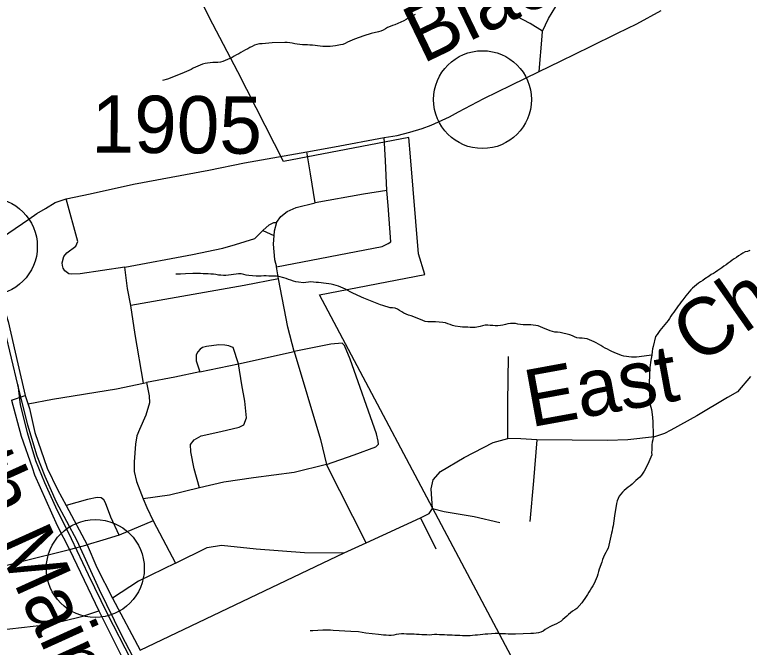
# Model space of a CAD drawing. Extents: x 1379453 to 1387082, y 594364 to 596664.
# Drawn here: x 1380115.2 to 1380304.5, y 596180.5 to 596343.6 of the extents above; entities that cross this region are included whole.
import ezdxf

# ---------------------------------------------------------------- set-up
doc = ezdxf.new("R2010")
doc.units = 0
for name, color, linetype in [('Old_Level_11', 7, 'Continuous'), ('Old_Level_29', 7, 'Continuous'), ('Old_Level_32', 7, 'Continuous'), ('Old_Level_35', 7, 'Continuous'), ('Old_Level_44', 7, 'Continuous'), ('Old_Level_48', 7, 'Continuous'), ('Old_Level_49', 7, 'Continuous'), ('Old_Level_62', 7, 'Continuous'), ('Old_Level_8', 7, 'Continuous')]:
    doc.layers.add(name, color=color, linetype=linetype)

msp = doc.modelspace()

# ---------------------------------------------------------------- linework, layer by layer
at = {"layer": 'Old_Level_29'}
for points in [[(1380108.46, 596283.82), (1380111.76, 596270.24), (1380113.55, 596264.52), (1380116.02, 596253.56), (1380117.97, 596245.42)], [(1380117.97, 596245.42), (1380119.03, 596242.08), (1380120.4, 596235.9), (1380123.6, 596226.7), (1380126.24, 596221.18), (1380128.47, 596217.04), (1380133.91, 596206.95)], [(1380133.91, 596206.95), (1380136.38, 596201.11), (1380140.4, 596193.23), (1380147.53, 596179.82)]]:
    msp.add_lwpolyline(points, dxfattribs=at)
at = {"layer": 'Old_Level_32'}
for p, q in [((1380114.41, 596244.19), (1380117.97, 596245.42)), ((1380129.39, 596205.72), (1380133.91, 596206.95))]:
    msp.add_line(p, q, dxfattribs=at)
for points in [[(1380108.46, 596283.82), (1380118.87, 596290.87), (1380120.9, 596292.35), (1380123.15, 596293.62), (1380125.67, 596295.15), (1380128.47, 596296.14), (1380134.69, 596297.38), (1380145.88, 596299.86), (1380165.23, 596303.54), (1380174.41, 596305.44), (1380190.5, 596308.25), (1380197.64, 596309.56), (1380210.38, 596311.91), (1380213.74, 596312.43), (1380217.05, 596313.31), (1380220.2, 596314.25), (1380222.51, 596315.09), (1380227.24, 596317.29), (1380229.53, 596318.56), (1380236.12, 596321.94), (1380243.15, 596325.43), (1380250.35, 596328.92), (1380255.87, 596331.62), (1380263.54, 596335.36), (1380270.53, 596338.81), (1380275.52, 596341.25), (1380281.78, 596344.7)], [(1380242.31, 596234.37), (1380242.26, 596243.65), (1380242.48, 596255.48)], [(1380304.79, 596250.29), (1380301.41, 596246.4), (1380298.84, 596244.9), (1380291, 596240.23), (1380284.25, 596236.51), (1380282.6, 596235.67), (1380280.03, 596234.79), (1380273.2, 596234.03), (1380267.91, 596233.86), (1380249.74, 596234)], [(1380114.41, 596244.19), (1380116.9, 596234.95), (1380119.71, 596226.84), (1380120.31, 596224.99), (1380126.21, 596211.97), (1380129.39, 596205.72)], [(1380249.74, 596234), (1380245.59, 596234.27), (1380242.31, 596234.37)], [(1380249.74, 596234), (1380248.85, 596223.47), (1380247.95, 596212.95)], [(1380026.39, 596181.13), (1380049.77, 596192.89), (1380056.42, 596196.44), (1380059.77, 596198.34), (1380063.44, 596200.24), (1380066.91, 596200.02), (1380069.73, 596199.5), (1380071.26, 596198.68), (1380073.42, 596196.48), (1380075.56, 596193.36), (1380079.48, 596193.92), (1380087.21, 596195.33), (1380090.9, 596196.15), (1380093.23, 596196.62), (1380116.89, 596202.64), (1380129.39, 596205.72)], [(1380129.39, 596205.72), (1380136.89, 596189.9), (1380142.92, 596177.94)]]:
    msp.add_lwpolyline(points, dxfattribs=at)
for centre in [(1380235.75, 596321.69), (1380108.46, 596283.82), (1380136.01, 596200.86)]:
    msp.add_circle(centre, 12.61, dxfattribs=at)
at = {"layer": 'Old_Level_35'}
for p, q in [((1380179.2, 596287.95), (1380181.99, 596286.69)), ((1380183.22, 596275.48), (1380182.66, 596278.59)), ((1380172.93, 596253.58), (1380187.24, 596256.79)), ((1380162.91, 596251.56), (1380172.93, 596253.58)), ((1380148.43, 596248.59), (1380149.2, 596248.75)), ((1380205.74, 596207.5), (1380195.52, 596227.64)), ((1380150.9, 596213.17), (1380142.16, 596209.41)), ((1380150.9, 596213.17), (1380156.64, 596202.2)), ((1380205.74, 596207.5), (1380219.74, 596213.92)), ((1380219.74, 596213.92), (1380223.74, 596205.9)), ((1380200.14, 596204.85), (1380205.74, 596207.5))]:
    msp.add_line(p, q, dxfattribs=at)
for points in [[(1380251.23, 596339.32), (1380252.72, 596342.56), (1380254.63, 596345.69), (1380255.48, 596347.21)], [(1380251.23, 596339.32), (1380248, 596341.28), (1380244.56, 596343.14)], [(1380250.35, 596328.92), (1380251.11, 596338.01), (1380251.23, 596339.32)], [(1380211.09, 596298.26), (1380210.78, 596305.98), (1380210.38, 596311.91)], [(1380192.62, 596295.07), (1380191.46, 596302.53), (1380190.5, 596308.25)], [(1380182.66, 596278.59), (1380209.89, 596283.86), (1380211.48, 596284.58), (1380212.15, 596285.06), (1380211.48, 596294.43), (1380211.09, 596298.26)], [(1380211.09, 596298.26), (1380205.05, 596297.33), (1380192.62, 596295.07)], [(1380143.61, 596278.55), (1380132.1, 596276.81), (1380129.78, 596276.71), (1380129.22, 596276.81), (1380128.12, 596277.56), (1380127.74, 596278.21), (1380127.53, 596278.94), (1380127.47, 596279.66), (1380127.92, 596281.25), (1380128.66, 596282.19), (1380131.03, 596283.96), (1380131.47, 596285.15), (1380128.47, 596296.14)], [(1380182.69, 596290.05), (1380183.8, 596291.59), (1380185.41, 596292.82), (1380187.73, 596293.92), (1380192.62, 596295.07)], [(1380179.2, 596287.95), (1380180.76, 596289.44), (1380181.99, 596290.05), (1380182.69, 596290.05)], [(1380182.69, 596290.05), (1380182.06, 596287.81), (1380181.99, 596286.69)], [(1380143.61, 596278.55), (1380161, 596281.81), (1380168.89, 596283.42), (1380172.11, 596284.37), (1380177.08, 596285.92), (1380179.2, 596287.95)], [(1380181.99, 596286.69), (1380181.84, 596284.45), (1380182.2, 596280.47), (1380182.66, 596278.59)], [(1380145.16, 596268.66), (1380144.32, 596273.01), (1380143.61, 596278.55)], [(1380183.22, 596275.48), (1380174.37, 596273.82), (1380145.16, 596268.66)], [(1380187.24, 596256.79), (1380185.58, 596263.08), (1380183.22, 596275.48)], [(1380148.43, 596248.59), (1380146.3, 596261.19), (1380145.16, 596268.66)], [(1380172.93, 596253.58), (1380171.55, 596257.8), (1380171.03, 596257.98), (1380170.39, 596258.24), (1380169.36, 596258.43), (1380167.84, 596258.47), (1380164.62, 596258.08), (1380163.66, 596257.79), (1380163, 596257.34), (1380162.43, 596256.72), (1380162, 596255.93), (1380161.96, 596254.41), (1380162.91, 596251.56)], [(1380195.52, 596227.64), (1380202.69, 596230.13), (1380208.23, 596232.2), (1380208.94, 596232.88), (1380208.9, 596233.66), (1380208.4, 596235.52), (1380201.68, 596254.84), (1380200.18, 596258.34), (1380199.63, 596258.91), (1380196.66, 596258.68), (1380187.24, 596256.79)], [(1380187.24, 596256.79), (1380194.03, 596234.12), (1380195.52, 596227.64)], [(1380162.87, 596221.63), (1380161.47, 596226.56), (1380160.63, 596230.91), (1380160.53, 596232.83), (1380161.44, 596234.01), (1380163.31, 596235.07), (1380168.38, 596236.12), (1380173.06, 596237.27), (1380174.28, 596237.88), (1380174.98, 596239.7), (1380174.54, 596243.95), (1380173.78, 596248.14), (1380172.93, 596253.58)], [(1380162.91, 596251.56), (1380156.53, 596250.12), (1380149.2, 596248.75)], [(1380149.2, 596248.75), (1380149.88, 596245.32), (1380149.99, 596243.52), (1380149, 596240.35), (1380147.43, 596236.69), (1380146.74, 596235.02), (1380146.37, 596232.9), (1380145.99, 596228.37), (1380146, 596225.81), (1380146.64, 596223.23), (1380148.37, 596218.82)], [(1380118.71, 596243.28), (1380125.01, 596244.47), (1380141.43, 596247.14), (1380148.43, 596248.59)], [(1380222.89, 596216.29), (1380222.56, 596221.39), (1380223.02, 596223.72), (1380224.93, 596225.83), (1380231.04, 596229.49), (1380238.51, 596233.35), (1380242.31, 596234.37)], [(1380195.52, 596227.64), (1380187.19, 596225.59), (1380176.78, 596224.18), (1380169.1, 596223.07), (1380162.87, 596221.63)], [(1380162.87, 596221.63), (1380155.12, 596219.76), (1380148.37, 596218.82)], [(1380142.16, 596209.41), (1380139.99, 596214.1), (1380138.61, 596217.78), (1380138.17, 596218.53), (1380137.53, 596219.04), (1380136.51, 596219.11), (1380134.02, 596218.63), (1380128.47, 596217.04)], [(1380148.37, 596218.82), (1380149.24, 596216.58), (1380150.9, 596213.17)], [(1380219.74, 596213.92), (1380220.99, 596214.5), (1380221.97, 596215.03), (1380222.89, 596216.29)], [(1380222.89, 596216.29), (1380225.91, 596215.55), (1380233.64, 596214.29), (1380240.24, 596212.73)], [(1380142.16, 596209.41), (1380137.92, 596208.14), (1380133.91, 596206.95)], [(1380156.64, 596202.2), (1380164.79, 596206.28), (1380168.49, 596206.82), (1380177.44, 596205.92), (1380189.9, 596204.99), (1380200.14, 596204.85)], [(1380147.53, 596179.82), (1380192.75, 596201.39), (1380200.14, 596204.85)], [(1380156.64, 596202.2), (1380147.09, 596197.6), (1380140.4, 596193.23)], [(1380081.13, 596177.69), (1380088.66, 596180.11), (1380095.22, 596182.48), (1380100.19, 596184.55), (1380113.97, 596185.32), (1380122.99, 596186.36), (1380127.57, 596187.25), (1380132.78, 596188.54), (1380136.89, 596189.9)]]:
    msp.add_lwpolyline(points, dxfattribs=at)
at = {"layer": 'Old_Level_44'}
for points in [[(1380116.06, 596248.21), (1380112.78, 596261.93), (1380109.32, 596275.15), (1380106.26, 596288.21), (1380103.83, 596298.21), (1380102.17, 596307.22), (1380102.03, 596316.04), (1380101.94, 596323.8), (1380102.14, 596330.6), (1380103.22, 596337.78), (1380105.24, 596346.36), (1380107.03, 596355.59), (1380107.3, 596362.39), (1380107.51, 596369.43), (1380106.53, 596377.3), (1380104.36, 596387.78), (1380101.51, 596396.99), (1380098.46, 596405.32), (1380096.21, 596409.95), (1380082.73, 596438.92), (1380082.12, 596440.37)], [(1380198.66, 596068.96), (1380192.47, 596082.12), (1380185.52, 596096.08), (1380177.44, 596112.65), (1380169.29, 596129.78), (1380163.55, 596141.56), (1380160.14, 596148.38), (1380153.87, 596161.13), (1380148.6, 596172.57), (1380142.84, 596183.55), (1380137.1, 596195.32), (1380131.3, 596207.98), (1380125.99, 596217.98), (1380123.06, 596224.56), (1380121.05, 596229.82), (1380118.64, 596237.81), (1380116.06, 596248.21), (1380112.78, 596261.93)], [(1380163.55, 596141.56), (1380160.14, 596148.38), (1380153.87, 596161.13), (1380148.6, 596172.57), (1380142.84, 596183.55), (1380137.1, 596195.32), (1380131.3, 596207.98), (1380125.99, 596217.98), (1380123.06, 596224.56), (1380121.05, 596229.82), (1380118.64, 596237.81), (1380116.06, 596248.21)], [(1380116.06, 596248.21), (1380116.64, 596243.07), (1380118.43, 596235.9), (1380120.62, 596228.71), (1380122.93, 596223.04), (1380125.71, 596216.71), (1380129.8, 596208.59), (1380134.17, 596199.34), (1380139.09, 596189.26), (1380145.14, 596177.4), (1380151.41, 596164.24), (1380156.93, 596153.36), (1380161.54, 596144.25), (1380163.55, 596141.56)]]:
    msp.add_lwpolyline(points, dxfattribs=at)
at = {"layer": 'Old_Level_48'}
msp.add_line((1380172.72, 596328.84), (1380166.28, 596341.14), dxfattribs=at)
for points in [[(1380166.28, 596341.14), (1380159.53, 596354.69)], [(1380306.1, 595961.49), (1380283.01, 595983.98), (1380282.74, 595991.87), (1380288.32, 596012.89), (1380266.64, 596016.44), (1380270.23, 596027.03), (1380285.74, 596075.63), (1380291.22, 596074.09), (1380294.95, 596086.05), (1380302.91, 596083.24), (1380314.44, 596118.5), (1380286.73, 596124.3), (1380274.6, 596118.89), (1380271.54, 596124.6), (1380193.74, 596271.38), (1380220.87, 596276.59), (1380219.29, 596281.97), (1380217.17, 596306.95), (1380216.79, 596311.89), (1380184.45, 596305.78), (1380172.72, 596328.84)]]:
    msp.add_lwpolyline(points, dxfattribs=at)
at = {"layer": 'Old_Level_49'}
msp.add_line((1380172.72, 596328.84), (1380166.28, 596341.14), dxfattribs=at)
for points in [[(1380166.28, 596341.14), (1380159.53, 596354.69)], [(1380306.1, 595961.49), (1380283.01, 595983.98), (1380282.74, 595991.87), (1380288.32, 596012.89), (1380266.64, 596016.44), (1380270.23, 596027.03), (1380285.74, 596075.63), (1380291.22, 596074.09), (1380294.95, 596086.05), (1380302.91, 596083.24), (1380314.44, 596118.5), (1380286.73, 596124.3), (1380274.6, 596118.89), (1380271.54, 596124.6), (1380193.74, 596271.38), (1380220.87, 596276.59), (1380219.29, 596281.97), (1380217.17, 596306.95), (1380216.79, 596311.89), (1380184.45, 596305.78), (1380172.72, 596328.84)]]:
    msp.add_lwpolyline(points, dxfattribs=at)
at = {"layer": 'Old_Level_62'}
for points in [[(1380218.38, 596343.6), (1380217.78, 596343.33), (1380217.2, 596343.02), (1380216.63, 596342.69), (1380216.07, 596342.35), (1380215.51, 596342), (1380213.16, 596340.96), (1380212.53, 596340.76), (1380211.92, 596340.54), (1380211.31, 596340.28), (1380210.74, 596339.95), (1380210.17, 596339.61), (1380209.59, 596339.34), (1380208.95, 596339.18), (1380207.03, 596338.71), (1380205.18, 596338.12), (1380203.96, 596337.72), (1380202.74, 596337.31), (1380202.14, 596337.04), (1380201.55, 596336.75), (1380200.96, 596336.46), (1380200.36, 596336.18), (1380199.76, 596335.93), (1380199.13, 596335.79), (1380197.84, 596335.58), (1380197.19, 596335.49), (1380196.54, 596335.41), (1380195.88, 596335.36), (1380195.23, 596335.35), (1380194.58, 596335.4), (1380193.93, 596335.47), (1380193.27, 596335.56), (1380192.62, 596335.65), (1380191.97, 596335.72), (1380191.31, 596335.76), (1380190.65, 596335.79), (1380190, 596335.82), (1380189.35, 596335.85), (1380188.69, 596335.9), (1380188.04, 596335.97), (1380187.39, 596336.1), (1380186.75, 596336.25), (1380186.11, 596336.35), (1380185.45, 596336.39), (1380184.79, 596336.39), (1380181.54, 596336.34), (1380178.95, 596336.1), (1380178.3, 596336.03), (1380177.65, 596335.91), (1380177.03, 596335.7), (1380176.44, 596335.42), (1380175.85, 596335.12), (1380175.27, 596334.82), (1380174.69, 596334.5), (1380174.11, 596334.18), (1380173.53, 596333.86), (1380172.96, 596333.53), (1380172.38, 596333.21), (1380171.8, 596332.89), (1380171.22, 596332.59), (1380170.64, 596332.29), (1380170.05, 596332), (1380169.45, 596331.74), (1380168.86, 596331.49), (1380168.24, 596331.32), (1380167.59, 596331.27)], [(1380167.59, 596331.27), (1380166.92, 596331.26), (1380166.25, 596331.25), (1380165.59, 596331.2), (1380164.94, 596331.1), (1380164.29, 596330.98), (1380163.65, 596330.82), (1380163.05, 596330.58), (1380162.44, 596330.33), (1380161.84, 596330.06), (1380161.25, 596329.78), (1380160.66, 596329.49), (1380158.26, 596328.43), (1380154.6, 596326.98), (1380153.34, 596326.59)], [(1380304.58, 596282.78), (1380303.97, 596282.56), (1380303.39, 596282.44), (1380302.82, 596282.11), (1380302.27, 596281.76), (1380301.71, 596281.4), (1380301.16, 596281.03), (1380300.62, 596280.67), (1380300.08, 596280.29), (1380299.54, 596279.91), (1380299.01, 596279.53), (1380298.48, 596279.14), (1380297.95, 596278.75), (1380297.42, 596278.37), (1380296.88, 596277.99), (1380296.35, 596277.61), (1380295.8, 596277.24), (1380295.24, 596276.91), (1380294.67, 596276.58), (1380294.12, 596276.22), (1380293.03, 596275.48), (1380292.48, 596275.11), (1380291.94, 596274.74), (1380291.4, 596274.36), (1380290.88, 596273.97), (1380290.37, 596273.55), (1380289.88, 596273.13), (1380289.42, 596272.67), (1380288.98, 596272.18), (1380288.56, 596271.67), (1380288.15, 596271.15), (1380287.35, 596270.11), (1380286.95, 596269.59), (1380286.56, 596269.06), (1380286.16, 596268.53), (1380285.78, 596268), (1380285.4, 596267.47), (1380285.01, 596266.93), (1380284.64, 596266.4), (1380284.26, 596265.86), (1380283.92, 596265.3), (1380283.56, 596264.75), (1380283.15, 596264.23), (1380282.73, 596263.74), (1380282.31, 596263.24), (1380281.88, 596262.73), (1380281.47, 596262.22), (1380281.08, 596261.69), (1380280.7, 596261.15), (1380280.33, 596260.61), (1380279.72, 596258.08), (1380279.58, 596257.44), (1380279.48, 596256.79), (1380279.33, 596255.87)], [(1380204.6, 596270.79), (1380202.21, 596271.87), (1380201.62, 596272.16), (1380201.05, 596272.48), (1380200.48, 596272.81), (1380199.89, 596273.11), (1380199.29, 596273.36), (1380198.67, 596273.6), (1380198.05, 596273.8), (1380197.41, 596273.97), (1380196.77, 596274.09), (1380196.13, 596274.2), (1380195.47, 596274.3), (1380194.83, 596274.39), (1380194.17, 596274.47), (1380193.51, 596274.54), (1380192.86, 596274.6), (1380192.21, 596274.65), (1380191.55, 596274.69), (1380190.9, 596274.67), (1380190.25, 596274.53), (1380189.61, 596274.45), (1380188.32, 596274.64), (1380187.68, 596274.77), (1380187.04, 596274.94), (1380186.41, 596275.12), (1380185.78, 596275.31), (1380185.19, 596275.58), (1380184.58, 596275.8), (1380183.31, 596276.1), (1380182.66, 596276.15), (1380182.01, 596276.18), (1380181.35, 596276.21), (1380180.69, 596276.23), (1380180.03, 596276.25), (1380179.38, 596276.26), (1380178.73, 596276.23), (1380177.45, 596276.18), (1380175.52, 596276.36), (1380174.87, 596276.44), (1380174.23, 596276.61), (1380173.58, 596276.76), (1380172.93, 596276.76), (1380172.29, 596276.7), (1380171.63, 596276.61), (1380170.98, 596276.51), (1380170.33, 596276.43), (1380169.67, 596276.4), (1380169.02, 596276.4), (1380168.36, 596276.43), (1380167.7, 596276.48), (1380167.07, 596276.64), (1380166.42, 596276.71), (1380165.77, 596276.74), (1380165.11, 596276.77), (1380164.45, 596276.8), (1380163.8, 596276.82), (1380163.14, 596276.84), (1380162.48, 596276.86), (1380161.83, 596276.87), (1380161.17, 596276.88), (1380159.22, 596276.79), (1380157.92, 596276.71), (1380156.75, 596276.71)], [(1380279.33, 596255.87), (1380278.68, 596255.78), (1380278.03, 596255.69), (1380277.38, 596255.58), (1380276.73, 596255.49), (1380276.08, 596255.41), (1380275.42, 596255.34), (1380274.78, 596255.31), (1380274.12, 596255.32), (1380273.46, 596255.38), (1380272.81, 596255.48), (1380272.17, 596255.61), (1380271.53, 596255.78), (1380270.91, 596255.99), (1380270.3, 596256.23), (1380269.69, 596256.49), (1380269.1, 596256.76), (1380268.51, 596257.05), (1380267.92, 596257.35), (1380267.34, 596257.66), (1380266.77, 596257.98), (1380266.21, 596258.32), (1380265.65, 596258.66), (1380265.07, 596258.98), (1380264.48, 596259.25), (1380262.7, 596260.07), (1380262.05, 596260.13), (1380261.39, 596260.17), (1380260.73, 596260.21), (1380260.09, 596260.31), (1380259.48, 596260.54), (1380258.89, 596260.84), (1380258.28, 596261.06), (1380255.72, 596261.66), (1380255.08, 596261.78), (1380254.42, 596261.78), (1380253.79, 596261.94), (1380253.16, 596262.14), (1380252.54, 596262.36), (1380251.92, 596262.59), (1380251.33, 596262.87), (1380250.73, 596263.14), (1380250.1, 596263.35), (1380249.47, 596263.51), (1380248.82, 596263.6), (1380248.17, 596263.63), (1380247.51, 596263.64), (1380246.85, 596263.65), (1380246.19, 596263.67), (1380245.54, 596263.73), (1380244.88, 596263.84), (1380244.23, 596263.95), (1380243.59, 596264.02), (1380242.94, 596264), (1380242.29, 596263.89), (1380241.65, 596263.74), (1380241.01, 596263.58), (1380240.36, 596263.45), (1380239.71, 596263.39), (1380239.05, 596263.39), (1380238.4, 596263.44), (1380237.74, 596263.5), (1380237.08, 596263.54), (1380236.43, 596263.54), (1380235.79, 596263.42), (1380235.17, 596263.19), (1380233.9, 596262.98), (1380233.25, 596262.98), (1380232.59, 596263), (1380231.93, 596263.02), (1380231.27, 596263.04), (1380230.62, 596263.07), (1380229.96, 596263.11), (1380228.69, 596263.3), (1380228.06, 596263.46), (1380227.45, 596263.7), (1380226.83, 596263.94), (1380226.21, 596264.15), (1380225.57, 596264.27), (1380223.63, 596264.46), (1380222.97, 596264.44), (1380222.3, 596264.4), (1380221.65, 596264.41), (1380221.01, 596264.54), (1380220.41, 596264.77), (1380219.81, 596265.06), (1380217.34, 596265.97), (1380216.71, 596266.15), (1380216.1, 596266.39), (1380215.52, 596266.69), (1380214.95, 596267.03), (1380214.39, 596267.37), (1380213.81, 596267.68), (1380213.21, 596267.93), (1380212.55, 596268.03), (1380211.93, 596267.99), (1380210.07, 596268.61), (1380209.46, 596268.83), (1380205.21, 596270.56), (1380204.6, 596270.79)], [(1380279.33, 596255.87), (1380279.11, 596254.58), (1380279.01, 596253.93), (1380278.94, 596253.28), (1380278.88, 596252.62), (1380278.84, 596251.97), (1380278.79, 596251.32), (1380278.76, 596250.66), (1380278.73, 596250), (1380278.7, 596249.35), (1380278.7, 596248.69), (1380278.69, 596248.04), (1380278.7, 596247.38), (1380278.72, 596246.72), (1380278.76, 596246.07), (1380278.85, 596244.37), (1380278.83, 596243.71), (1380278.91, 596243.06), (1380279.09, 596242.43), (1380279.26, 596241.8), (1380279.51, 596239.86), (1380279.63, 596238.58), (1380279.71, 596235.32), (1380279.7, 596234.66), (1380279.65, 596234.01), (1380279.45, 596233.4), (1380279.4, 596232.74), (1380279.36, 596232.09), (1380279.33, 596231.43), (1380279.3, 596230.77), (1380279.36, 596230.12), (1380279.13, 596229.52), (1380278.86, 596228.92), (1380278.59, 596228.32), (1380278.32, 596227.71), (1380278.03, 596227.12), (1380277.73, 596226.53), (1380277.41, 596225.96), (1380277.06, 596225.41), (1380276.68, 596224.89), (1380276.24, 596224.4), (1380275.78, 596223.93), (1380275.28, 596223.49), (1380274.29, 596222.61), (1380273.79, 596222.19), (1380273.26, 596221.8), (1380272.72, 596221.41), (1380272.22, 596220.99), (1380271.77, 596220.53), (1380271.35, 596220.01), (1380270.99, 596219.45), (1380270.69, 596218.87), (1380270.46, 596218.26), (1380270.29, 596217.62), (1380270.14, 596216.98), (1380269.84, 596215.06), (1380269.78, 596214.41), (1380269.59, 596213.12), (1380269.38, 596211.84), (1380269.25, 596211.2), (1380269.12, 596210.56), (1380268.97, 596209.91), (1380268.08, 596206.11), (1380267.8, 596205.52), (1380267.51, 596204.93), (1380267.21, 596204.34), (1380266.93, 596203.75), (1380266.69, 596203.14), (1380266.45, 596202.52), (1380265.81, 596200.69), (1380265.64, 596200.06), (1380265.47, 596199.42), (1380265.29, 596198.78), (1380265.07, 596198.17), (1380264.79, 596197.58), (1380264.49, 596196.99), (1380264.18, 596196.41), (1380263.85, 596195.84), (1380263.52, 596195.28), (1380263.18, 596194.71), (1380262.83, 596194.16), (1380262.48, 596193.61), (1380262.11, 596193.07), (1380261.72, 596192.54), (1380261.3, 596192.02), (1380260.06, 596190.53), (1380259.53, 596190.16), (1380258.96, 596189.81), (1380258.42, 596189.44), (1380257.92, 596189.02), (1380257.43, 596188.57), (1380256.95, 596188.11), (1380256.47, 596187.67), (1380255.97, 596187.25), (1380255.43, 596186.89), (1380254.85, 596186.57), (1380254.25, 596186.3), (1380253.65, 596186.04), (1380253.05, 596185.78), (1380252.46, 596185.48)], [(1380252.46, 596185.48), (1380251.91, 596185.1), (1380251.37, 596184.71), (1380250.8, 596184.41), (1380250.18, 596184.25), (1380249.53, 596184.16), (1380248.86, 596184.11), (1380248.2, 596184.08), (1380244.29, 596183.89), (1380243.64, 596183.9), (1380242.98, 596183.92), (1380242.33, 596183.95), (1380241.67, 596183.98), (1380241.01, 596184.01), (1380240.36, 596184.04), (1380239.7, 596184.07), (1380239.05, 596184.08), (1380237.11, 596183.96), (1380236.46, 596183.91), (1380235.8, 596183.84), (1380235.15, 596183.76), (1380234.5, 596183.68), (1380233.85, 596183.62), (1380233.2, 596183.56), (1380232.54, 596183.52), (1380231.88, 596183.51), (1380231.23, 596183.52), (1380230.57, 596183.52), (1380229.92, 596183.54), (1380229.26, 596183.57), (1380228.61, 596183.59), (1380227.95, 596183.63), (1380227.29, 596183.66), (1380226.63, 596183.69), (1380225.98, 596183.72), (1380225.32, 596183.76), (1380224.67, 596183.78), (1380224.01, 596183.81), (1380223.35, 596183.83), (1380222.71, 596183.71), (1380222.06, 596183.7), (1380221.4, 596183.72), (1380220.75, 596183.74), (1380220.09, 596183.78), (1380219.43, 596183.81), (1380218.78, 596183.84), (1380218.12, 596183.88), (1380217.46, 596183.91), (1380216.81, 596183.93), (1380216.15, 596183.95), (1380215.5, 596183.97), (1380214.84, 596183.97), (1380214.19, 596183.94), (1380213.54, 596183.84), (1380212.89, 596183.7), (1380212.24, 596183.6), (1380211.59, 596183.59), (1380210.94, 596183.62), (1380210.28, 596183.68), (1380209.63, 596183.74), (1380208.98, 596183.82), (1380205.71, 596184.19), (1380203.8, 596184.55), (1380201.85, 596184.65), (1380197.26, 596184.88), (1380196.61, 596184.91), (1380195.95, 596184.94), (1380195.3, 596184.96), (1380194.64, 596184.98), (1380193.34, 596184.86), (1380192.06, 596184.76), (1380191.38, 596184.78)]]:
    msp.add_lwpolyline(points, dxfattribs=at)

# ---------------------------------------------------------------- texts
at = {"layer": 'Old_Level_11'}
for s, height, rotation, p in [('Black', 14.764, 25.6884, (1380220.3, 596330.85)), ('Chestnut', 14.764, 35.0359, (1380291.43, 596253.04)), ('North Main St.', 14.7638, 294.3805, (1380087.91, 596256.7)), ('East', 14.764, 10.3403, (1380248.15, 596237.21))]:
    msp.add_text(s, height=height, rotation=rotation, dxfattribs=at).set_placement(p)
at = {"layer": 'Old_Level_8'}
msp.add_text('1905', height=14.764, rotation=359.52, dxfattribs=at).set_placement((1380134.97, 596308.07))

doc.saveas('drawing.dxf')
